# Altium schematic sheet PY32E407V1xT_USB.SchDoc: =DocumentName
size A3; Revision: V2.1; SheetNumber: 3; SheetTotal: 3
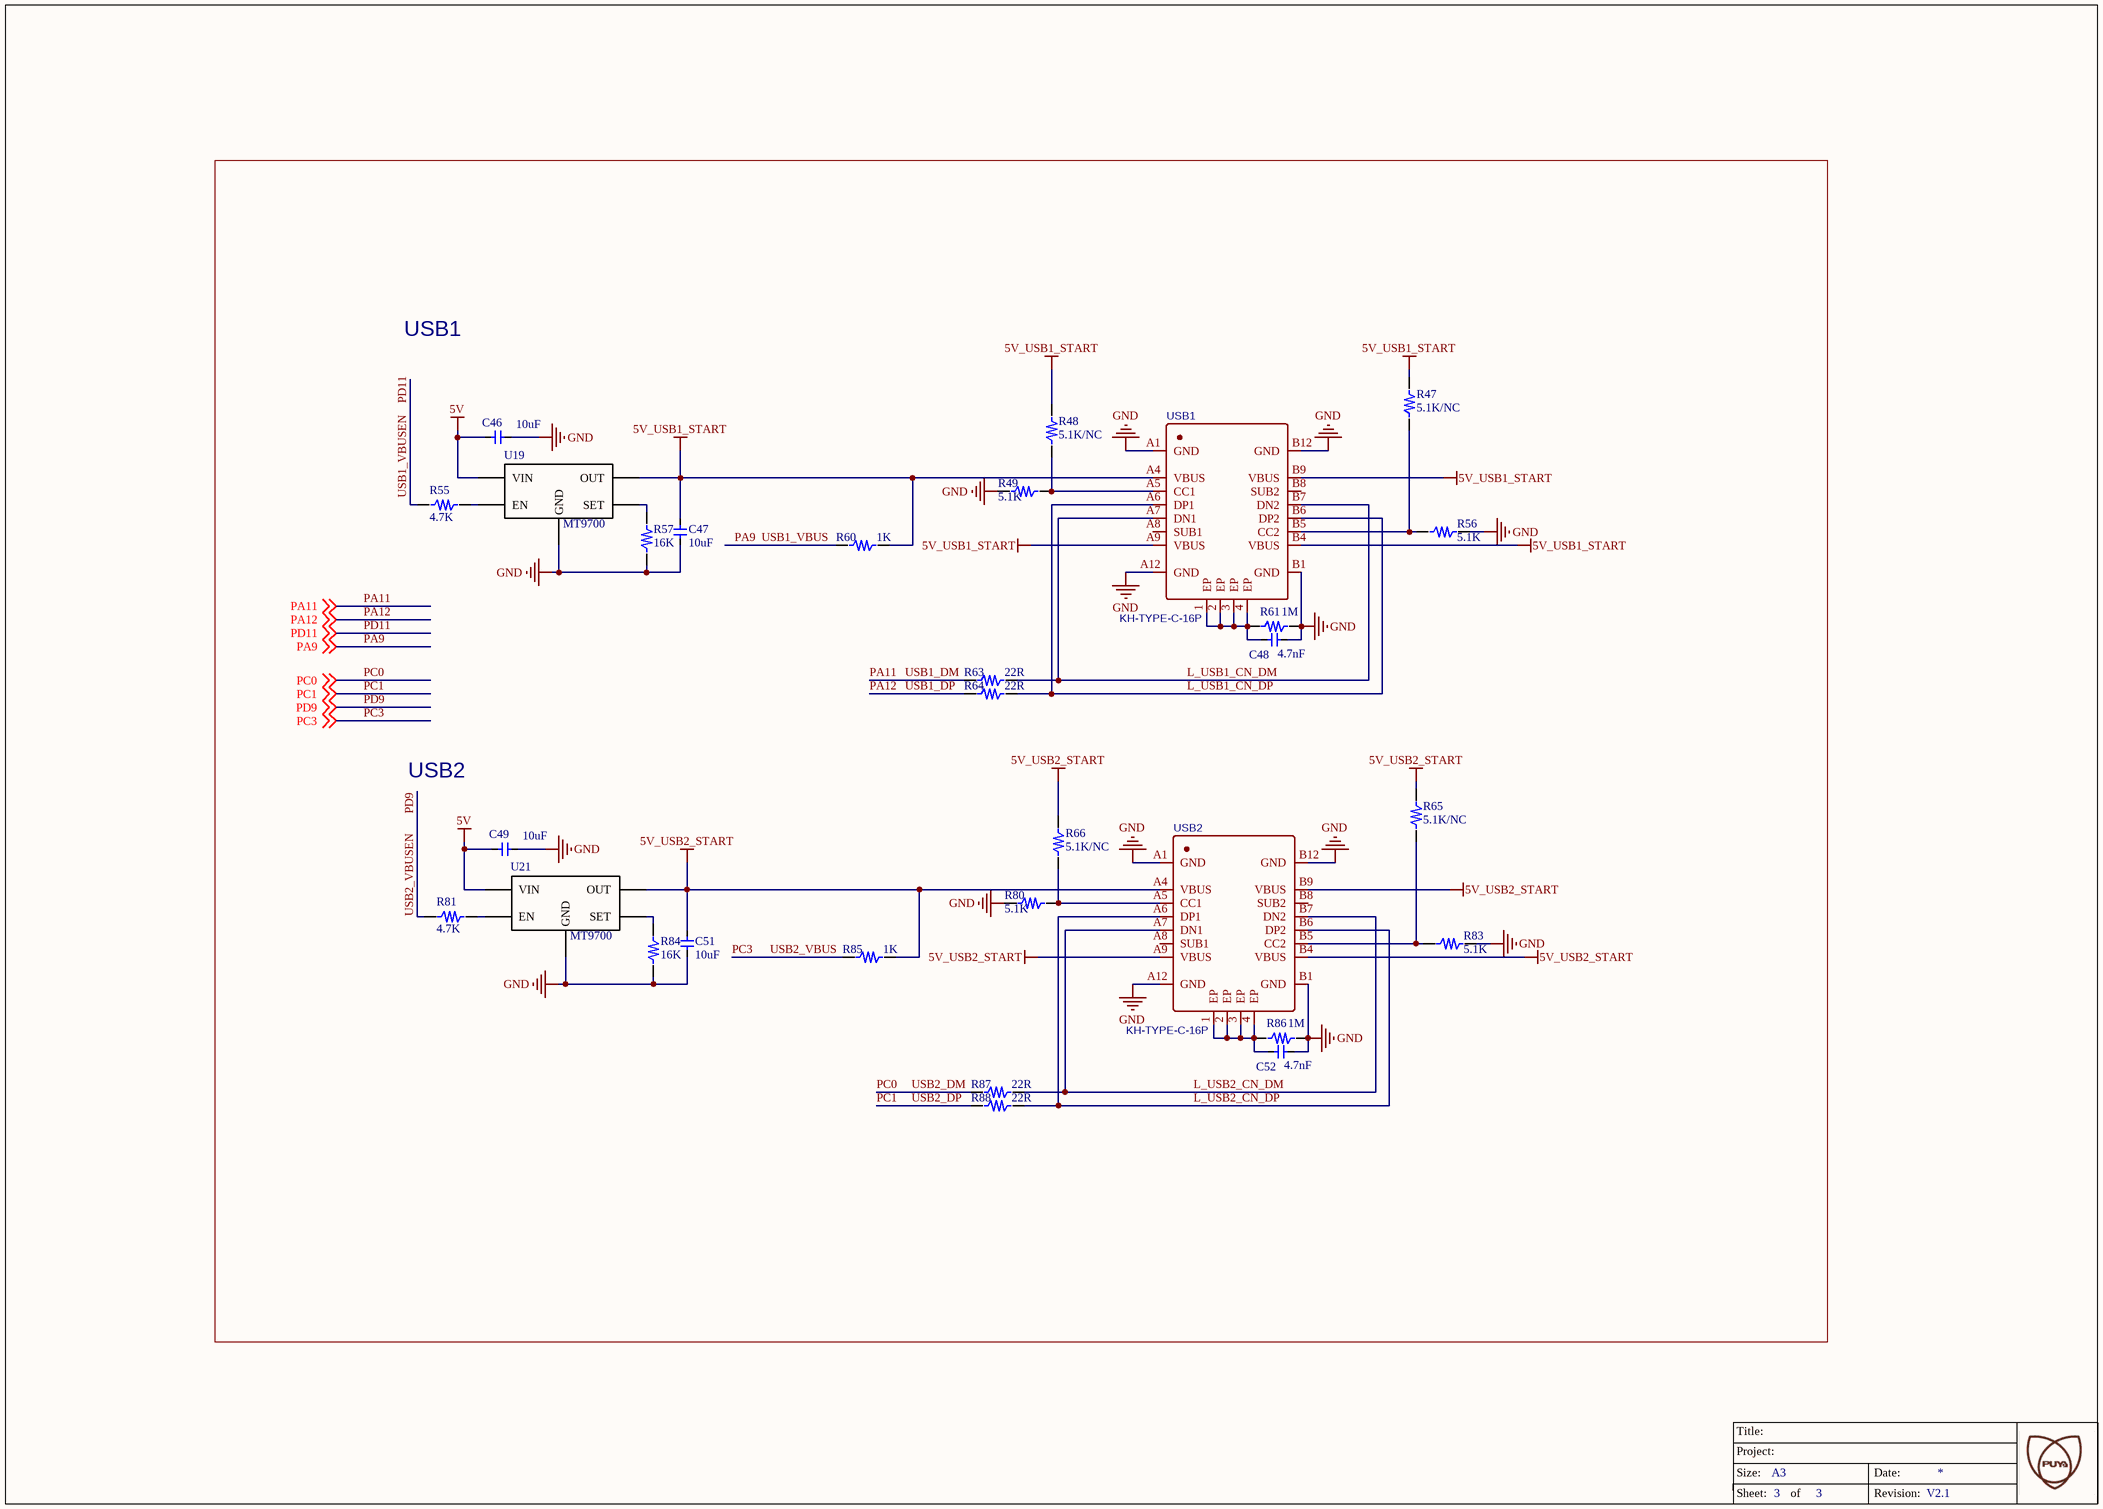
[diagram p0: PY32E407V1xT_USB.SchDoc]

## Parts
C46  10uF  [C0805]
C47  10uF  [C0805]
C48  4.7nF  [C0603]
C49  10uF  [C0805]
C51  10uF  [C0805]
C52  4.7nF  [C0603]
R47  5.1K/NC  [R0603]
R48  5.1K/NC  [R0603]
R49  5.1K  [R0603]
R55  4.7K  [R0603]
R56  5.1K  [R0603]
R57  16K  [R0603]
R60  1K  [R0603]
R61  1M  [R0603]
R63  22R  [R0603]
R64  22R  [R0603]
R65  5.1K/NC  [R0603]
R66  5.1K/NC  [R0603]
R80  5.1K  [R0603]
R81  4.7K  [R0603]
R83  5.1K  [R0603]
R84  16K  [R0603]
R85  1K  [R0603]
R86  1M  [R0603]
R87  22R  [R0603]
R88  22R  [R0603]
U19  MT9700  [SOT23-5]
U21  MT9700  [SOT23-5]
USB1  KH-TYPE-C-16P  [USB-C-SMD_KH-TYPE-C-16P]
USB2  KH-TYPE-C-16P  [USB-C-SMD_KH-TYPE-C-16P]

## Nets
5V: C46.2 C49.2 U19.5(VIN) U21.5(VIN)
5V_USB1_START: C47.2 R47.2 R48.2 R60.2 U19.1(OUT) USB1.A4(VBUS) USB1.A9(VBUS) USB1.B4(VBUS) USB1.B9(VBUS)
5V_USB2_START: C51.2 R65.2 R66.2 R85.2 U21.1(OUT) USB2.A4(VBUS) USB2.A9(VBUS) USB2.B4(VBUS) USB2.B9(VBUS)
GND: C46.1 C47.1 C48.1 C49.1 C51.1 C52.1 R49.1 R56.2 R57.1 R61.2 R80.1 R83.2 R84.1 R86.2 U19.2(GND) U21.2(GND) USB1.A1(GND) USB1.A12(GND) USB1.B1(GND) USB1.B12(GND) USB2.A1(GND) USB2.A12(GND) USB2.B1(GND) USB2.B12(GND)
L_USB1_CN_DM: R63.2 USB1.A7(DN1) USB1.B7(DN2)
L_USB1_CN_DP: R64.2 USB1.A6(DP1) USB1.B6(DP2)
L_USB2_CN_DM: R87.2 USB2.A7(DN1) USB2.B7(DN2)
L_USB2_CN_DP: R88.2 USB2.A6(DP1) USB2.B6(DP2)
PA9: R60.1 ; off-sheet PA9  [also labelled USB1_VBUS]
PA11: R63.1 ; off-sheet PA11  [also labelled USB1_DM]
PA12: R64.1 ; off-sheet PA12  [also labelled USB1_DP]
PC0: R87.1 ; off-sheet PC0  [also labelled USB2_DM]
PC1: R88.1 ; off-sheet PC1  [also labelled USB2_DP]
PC3: R85.1 ; off-sheet PC3  [also labelled USB2_VBUS]
PD9: R81.1 ; off-sheet PD9  [also labelled USB2_VBUSEN]
PD11: R55.1 ; off-sheet PD11  [also labelled USB1_VBUSEN]
NetC48_2: C48.2 R61.1 USB1.1(EP) USB1.2(EP) USB1.3(EP) USB1.4(EP)
NetC52_2: C52.2 R86.1 USB2.1(EP) USB2.2(EP) USB2.3(EP) USB2.4(EP)
NetR47_1: R47.1 R56.1 USB1.B5(CC2)
NetR48_1: R48.1 R49.2 USB1.A5(CC1)
NetR55_2: R55.2 U19.4(EN)
NetR57_2: R57.2 U19.3(SET)
NetR65_1: R65.1 R83.1 USB2.B5(CC2)
NetR66_1: R66.1 R80.2 USB2.A5(CC1)
NetR81_2: R81.2 U21.4(EN)
NetR84_2: R84.2 U21.3(SET)

Not connected (* = marked no-connect by the designer): USB1 A8(SUB1) B8(SUB2); USB2 A8(SUB1) B8(SUB2)

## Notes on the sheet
- USB1
- USB2

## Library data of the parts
C46 C47 C49 C51 = C0805: PCB DECAL: 0805
C48 C52 = C0603: PCB DECAL: 0603
R47-R49 R55-R57 R60 R61 R63-R66 R80 R81 R83-R88 = R0603: PCB DECAL: 0603
USB1 USB2 = KH-TYPE-C-16P: BOM_Manufacturer: Shenzhen Kinghelm Elec; Contributor: LCSC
